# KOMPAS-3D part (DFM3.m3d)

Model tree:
1. Эскиз:1
2. Операция выдавливания:1
     Расстояние 1 = 5.6
3. Эскиз:2
4. Операция выдавливания:2
     Расстояние 1 = 0.85; Угол 1 = 45
5. Эскиз:3
6. Эскиз:4
7. Эскиз:5
8. Эскиз:6
9. Эскиз:7
10. Операция выдавливания:3
     Расстояние 1 = 0.85; Угол 1 = 45
11. Операция выдавливания:4
     Расстояние 1 = 0.85; Угол 1 = 45
12. Вырезать элемент выдавливания:1
     Расстояние 1 = 0.85; Угол 1 = 45
13. Вырезать элемент выдавливания:2
     Расстояние 1 = 0.85; Угол 1 = 45
14. Вырезать элемент выдавливания:3
     Расстояние 1 = 0.85; Угол 1 = 45
15. Эскиз:8
16. Эскиз:9
17. Эскиз:10
18. Эскиз:11
19. Эскиз:12
20. Эскиз:13
21. Операция выдавливания:5
     Расстояние 1 = 0.85; Угол 1 = 45
22. Операция выдавливания:6
     Расстояние 1 = 0.85; Угол 1 = 45
23. Операция выдавливания:7
     Расстояние 1 = 0.85; Угол 1 = 45
24. Вырезать элемент выдавливания:4
     Расстояние 1 = 0.85; Угол 1 = 45
25. Вырезать элемент выдавливания:5
     Расстояние 1 = 0.85; Угол 1 = 45
26. Вырезать элемент выдавливания:6
     Расстояние 1 = 0.85; Угол 1 = 45
27. Массив по концентрической сетке:1  (with: Операция выдавливания:5, Операция выдавливания:6, Операция выдавливания:7, Вырезать элемент выдавливания:4, Вырезать элемент выдавливания:5, Вырезать элемент выдавливания:6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)  (5 pattern instances)
     Геометрический массив = 4; Шаг 2 = 360; Номер 2 = 1
28. Фаска:1
     Угол = 40; Длина 1 = 0.8; Длина 2 = 0.67128
29. Скругление:1
     Радиус = 2.8
30. Скругление:2
     Радиус = 0.9
